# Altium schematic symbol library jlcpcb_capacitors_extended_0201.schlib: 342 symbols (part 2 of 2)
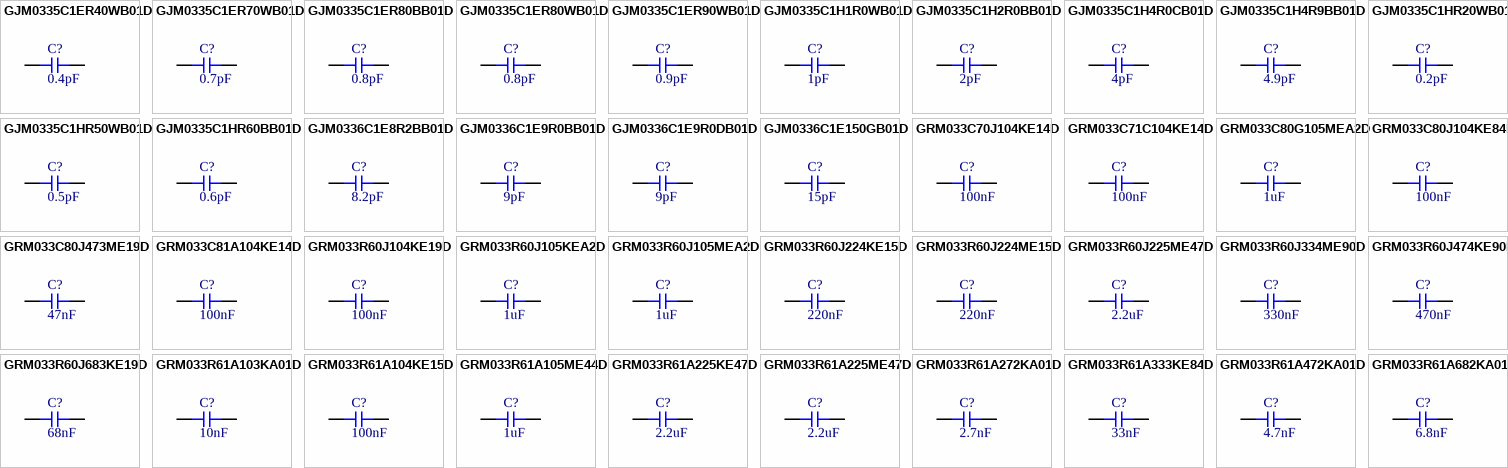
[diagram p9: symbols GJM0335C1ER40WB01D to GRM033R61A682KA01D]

## GRM033C81A104KE14D
designator C?  Capacitance: 100nF  (hidden comment: *)
Capacitor, Ceramic (MLCC), 100nF, ±10%, ±10%, SMD 0201; Manufacturer: Murata Electronics; Manufacturer Part Number: GRM033C81A104KE14D
footprint CAP-0201 (0201 (0603M) Capacitor)
pins: 1, 2

## GRM033R60J104KE19D
designator C?  Capacitance: 100nF  (hidden comment: *)
Capacitor, Ceramic (MLCC), 100nF, ±10%, 6.3V, X5R, ±10%, SMD 0201; Manufacturer: Murata Electronics; Manufacturer Part Number: GRM033R60J104KE19D
footprint CAP-0201 (0201 (0603M) Capacitor)
pins: 1, 2

## GRM033R60J105KEA2D
designator C?  Capacitance: 1uF  (hidden comment: *)
Capacitor, Ceramic (MLCC), 1uF, ±10%, 6.3V, X5R, ±10%, SMD 0201; Manufacturer: Murata Electronics; Manufacturer Part Number: GRM033R60J105KEA2D
footprint CAP-0201 (0201 (0603M) Capacitor)
pins: 1, 2

## GRM033R60J105MEA2D
designator C?  Capacitance: 1uF  (hidden comment: *)
Capacitor, Ceramic (MLCC), 1uF, ±20%, 6.3V, X5R, ±20%, SMD 0201; Manufacturer: Murata Electronics; Manufacturer Part Number: GRM033R60J105MEA2D
footprint CAP-0201 (0201 (0603M) Capacitor)
pins: 1, 2

## GRM033R60J224KE15D
designator C?  Capacitance: 220nF  (hidden comment: *)
Capacitor, Ceramic (MLCC), 220nF, ±10%, 6.3V, X5R, ±10%, SMD 0201; Manufacturer: Murata Electronics; Manufacturer Part Number: GRM033R60J224KE15D
footprint CAP-0201 (0201 (0603M) Capacitor)
pins: 1, 2

## GRM033R60J224ME15D
designator C?  Capacitance: 220nF  (hidden comment: *)
Capacitor, Ceramic (MLCC), 220nF, ±20%, 6.3V, X5R, ±20%, SMD 0201; Manufacturer: Murata Electronics; Manufacturer Part Number: GRM033R60J224ME15D
footprint CAP-0201 (0201 (0603M) Capacitor)
pins: 1, 2

## GRM033R60J225ME47D
designator C?  Capacitance: 2.2uF  (hidden comment: *)
Capacitor, Ceramic (MLCC), 2.2uF, ±20%, 6.3V, X5R, ±20%, SMD 0201; Manufacturer: Murata Electronics; Manufacturer Part Number: GRM033R60J225ME47D
footprint CAP-0201 (0201 (0603M) Capacitor)
pins: 1, 2

## GRM033R60J334ME90D
designator C?  Capacitance: 330nF  (hidden comment: *)
Capacitor, Ceramic (MLCC), 330nF, ±20%, 6.3V, X5R, ±20%, SMD 0201; Manufacturer: Murata Electronics; Manufacturer Part Number: GRM033R60J334ME90D
footprint CAP-0201 (0201 (0603M) Capacitor)
pins: 1, 2

## GRM033R60J474KE90D
designator C?  Capacitance: 470nF  (hidden comment: *)
Capacitor, Ceramic (MLCC), 470nF, ±10%, 6.3V, X5R, ±10%, SMD 0201; Manufacturer: Murata Electronics; Manufacturer Part Number: GRM033R60J474KE90D
footprint CAP-0201 (0201 (0603M) Capacitor)
pins: 1, 2

## GRM033R60J683KE19D
designator C?  Capacitance: 68nF  (hidden comment: *)
Capacitor, Ceramic (MLCC), 68nF, ±10%, 6.3V, X5R, ±10%, SMD 0201; Manufacturer: Murata Electronics; Manufacturer Part Number: GRM033R60J683KE19D
footprint CAP-0201 (0201 (0603M) Capacitor)
pins: 1, 2

## GRM033R61A103KA01D
designator C?  Capacitance: 10nF  (hidden comment: *)
Capacitor, Ceramic (MLCC), 10nF, ±10%, 10V, X5R, ±10%, SMD 0201; Manufacturer: Murata Electronics; Manufacturer Part Number: GRM033R61A103KA01D
footprint CAP-0201 (0201 (0603M) Capacitor)
pins: 1, 2

## GRM033R61A104KE15D
designator C?  Capacitance: 100nF  (hidden comment: *)
Capacitor, Ceramic (MLCC), 100nF, ±10%, 10V, X5R, ±10%, SMD 0201; Manufacturer: Murata Electronics; Manufacturer Part Number: GRM033R61A104KE15D
footprint CAP-0201 (0201 (0603M) Capacitor)
pins: 1, 2

## GRM033R61A105ME44D
designator C?  Capacitance: 1uF  (hidden comment: *)
Capacitor, Ceramic (MLCC), 1uF, ±20%, 10V, X5R, ±20%, SMD 0201; Manufacturer: Murata Electronics; Manufacturer Part Number: GRM033R61A105ME44D
footprint CAP-0201 (0201 (0603M) Capacitor)
pins: 1, 2

## GRM033R61A225KE47D
designator C?  Capacitance: 2.2uF  (hidden comment: *)
Capacitor, Ceramic (MLCC), 2.2uF, ±10%, 10V, X5R, ±10%, SMD 0201; Manufacturer: Murata Electronics; Manufacturer Part Number: GRM033R61A225KE47D
footprint CAP-0201 (0201 (0603M) Capacitor)
pins: 1, 2

## GRM033R61A225ME47D
designator C?  Capacitance: 2.2uF  (hidden comment: *)
Capacitor, Ceramic (MLCC), 2.2uF, ±20%, 10V, X5R, ±20%, SMD 0201; Manufacturer: Murata Electronics; Manufacturer Part Number: GRM033R61A225ME47D
footprint CAP-0201 (0201 (0603M) Capacitor)
pins: 1, 2

## GRM033R61A272KA01D
designator C?  Capacitance: 2.7nF  (hidden comment: *)
Capacitor, Ceramic (MLCC), 2.7nF, ±10%, ±10%, SMD 0201; Manufacturer: Murata Electronics; Manufacturer Part Number: GRM033R61A272KA01D
footprint CAP-0201 (0201 (0603M) Capacitor)
pins: 1, 2

## GRM033R61A333KE84D
designator C?  Capacitance: 33nF  (hidden comment: *)
Capacitor, Ceramic (MLCC), 33nF, ±10%, 10V, X5R, ±10%, SMD 0201; Manufacturer: Murata Electronics; Manufacturer Part Number: GRM033R61A333KE84D
footprint CAP-0201 (0201 (0603M) Capacitor)
pins: 1, 2

## GRM033R61A472KA01D
designator C?  Capacitance: 4.7nF  (hidden comment: *)
Capacitor, Ceramic (MLCC), 4.7nF, ±10%, 10V, X5R, ±10%, SMD 0201; Manufacturer: Murata Electronics; Manufacturer Part Number: GRM033R61A472KA01D
footprint CAP-0201 (0201 (0603M) Capacitor)
pins: 1, 2

## GRM033R61A682KA01D
designator C?  Capacitance: 6.8nF  (hidden comment: *)
Capacitor, Ceramic (MLCC), 6.8nF, ±10%, 10V, X5R, ±10%, SMD 0201; Manufacturer: Murata Electronics; Manufacturer Part Number: GRM033R61A682KA01D
footprint CAP-0201 (0201 (0603M) Capacitor)
pins: 1, 2

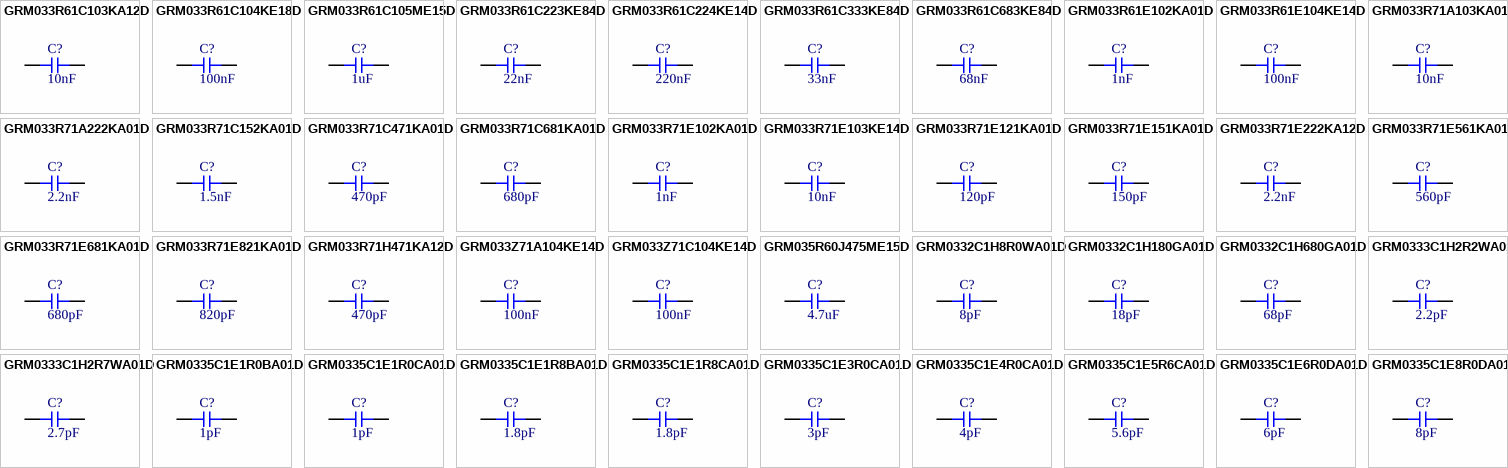
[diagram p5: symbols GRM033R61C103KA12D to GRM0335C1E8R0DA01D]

## GRM033R61C103KA12D
designator C?  Capacitance: 10nF  (hidden comment: *)
Capacitor, Ceramic (MLCC), 10nF, ±10%, 16V, X5R, ±10%, SMD 0201; Manufacturer: Murata Electronics; Manufacturer Part Number: GRM033R61C103KA12D
footprint CAP-0201 (0201 (0603M) Capacitor)
pins: 1, 2

## GRM033R61C104KE18D
designator C?  Capacitance: 100nF  (hidden comment: *)
Capacitor, Ceramic (MLCC), 100nF, ±10%, 16V, X5R, ±10%, SMD 0201; Manufacturer: Murata Electronics; Manufacturer Part Number: GRM033R61C104KE18D
footprint CAP-0201 (0201 (0603M) Capacitor)
pins: 1, 2

## GRM033R61C105ME15D
designator C?  Capacitance: 1uF  (hidden comment: *)
Capacitor, Ceramic (MLCC), 1uF, ±20%, 16V, X5R, ±20%, SMD 0201; Manufacturer: Murata Electronics; Manufacturer Part Number: GRM033R61C105ME15D
footprint CAP-0201 (0201 (0603M) Capacitor)
pins: 1, 2

## GRM033R61C223KE84D
designator C?  Capacitance: 22nF  (hidden comment: *)
Capacitor, Ceramic (MLCC), 22nF, ±10%, 16V, X5R, ±10%, SMD 0201; Manufacturer: Murata Electronics; Manufacturer Part Number: GRM033R61C223KE84D
footprint CAP-0201 (0201 (0603M) Capacitor)
pins: 1, 2

## GRM033R61C224KE14D
designator C?  Capacitance: 220nF  (hidden comment: *)
Capacitor, Ceramic (MLCC), 220nF, ±10%, 16V, X5R, ±10%, SMD 0201; Manufacturer: Murata Electronics; Manufacturer Part Number: GRM033R61C224KE14D
footprint CAP-0201 (0201 (0603M) Capacitor)
pins: 1, 2

## GRM033R61C333KE84D
designator C?  Capacitance: 33nF  (hidden comment: *)
Capacitor, Ceramic (MLCC), 33nF, ±10%, 16V, X5R, ±10%, SMD 0201; Manufacturer: Murata Electronics; Manufacturer Part Number: GRM033R61C333KE84D
footprint CAP-0201 (0201 (0603M) Capacitor)
pins: 1, 2

## GRM033R61C683KE84D
designator C?  Capacitance: 68nF  (hidden comment: *)
Capacitor, Ceramic (MLCC), 68nF, ±10%, 16V, ±10%, SMD 0201; Manufacturer: Murata Electronics; Manufacturer Part Number: GRM033R61C683KE84D
footprint CAP-0201 (0201 (0603M) Capacitor)
pins: 1, 2

## GRM033R61E102KA01D
designator C?  Capacitance: 1nF  (hidden comment: *)
Capacitor, Ceramic (MLCC), 1nF, ±10%, 25V, X5R, ±10%, SMD 0201; Manufacturer: Murata Electronics; Manufacturer Part Number: GRM033R61E102KA01D
footprint CAP-0201 (0201 (0603M) Capacitor)
pins: 1, 2

## GRM033R61E104KE14D
designator C?  Capacitance: 100nF  (hidden comment: *)
Capacitor, Ceramic (MLCC), 100nF, ±10%, 25V, X5R, ±10%, SMD 0201; Manufacturer: Murata Electronics; Manufacturer Part Number: GRM033R61E104KE14D
footprint CAP-0201 (0201 (0603M) Capacitor)
pins: 1, 2

## GRM033R71A103KA01D
designator C?  Capacitance: 10nF  (hidden comment: *)
Capacitor, Ceramic (MLCC), 10nF, ±10%, 10V, X7R, ±10%, SMD 0201; Manufacturer: Murata Electronics; Manufacturer Part Number: GRM033R71A103KA01D
footprint CAP-0201 (0201 (0603M) Capacitor)
pins: 1, 2

## GRM033R71A222KA01D
designator C?  Capacitance: 2.2nF  (hidden comment: *)
Capacitor, Ceramic (MLCC), 2.2nF, ±10%, 10V, X7R, ±10%, SMD 0201; Manufacturer: Murata Electronics; Manufacturer Part Number: GRM033R71A222KA01D
footprint CAP-0201 (0201 (0603M) Capacitor)
pins: 1, 2

## GRM033R71C152KA01D
designator C?  Capacitance: 1.5nF  (hidden comment: *)
Capacitor, Ceramic (MLCC), 1.5nF, ±10%, 16V, X7R, ±10%, SMD 0201; Manufacturer: Murata Electronics; Manufacturer Part Number: GRM033R71C152KA01D
footprint CAP-0201 (0201 (0603M) Capacitor)
pins: 1, 2

## GRM033R71C471KA01D
designator C?  Capacitance: 470pF  (hidden comment: *)
Capacitor, Ceramic (MLCC), 470pF, ±10%, 16V, X7R, ±10%, SMD 0201; Manufacturer: Murata Electronics; Manufacturer Part Number: GRM033R71C471KA01D
footprint CAP-0201 (0201 (0603M) Capacitor)
pins: 1, 2

## GRM033R71C681KA01D
designator C?  Capacitance: 680pF  (hidden comment: *)
Capacitor, Ceramic (MLCC), 680pF, ±10%, 16V, X7R, ±10%, SMD 0201; Manufacturer: Murata Electronics; Manufacturer Part Number: GRM033R71C681KA01D
footprint CAP-0201 (0201 (0603M) Capacitor)
pins: 1, 2

## GRM033R71E102KA01D
designator C?  Capacitance: 1nF  (hidden comment: *)
Capacitor, Ceramic (MLCC), 1nF, ±10%, 25V, X7R, ±10%, SMD 0201; Manufacturer: Murata Electronics; Manufacturer Part Number: GRM033R71E102KA01D
footprint CAP-0201 (0201 (0603M) Capacitor)
pins: 1, 2

## GRM033R71E103KE14D
designator C?  Capacitance: 10nF  (hidden comment: *)
Capacitor, Ceramic (MLCC), 10nF, ±10%, 25V, X7R, ±10%, SMD 0201; Manufacturer: Murata Electronics; Manufacturer Part Number: GRM033R71E103KE14D
footprint CAP-0201 (0201 (0603M) Capacitor)
pins: 1, 2

## GRM033R71E121KA01D
designator C?  Capacitance: 120pF  (hidden comment: *)
Capacitor, Ceramic (MLCC), 120pF, ±10%, 25V, ±10%, SMD 0201; Manufacturer: Murata Electronics; Manufacturer Part Number: GRM033R71E121KA01D
footprint CAP-0201 (0201 (0603M) Capacitor)
pins: 1, 2

## GRM033R71E151KA01D
designator C?  Capacitance: 150pF  (hidden comment: *)
Capacitor, Ceramic (MLCC), 150pF, ±10%, 25V, X7R, ±10%, SMD 0201; Manufacturer: Murata Electronics; Manufacturer Part Number: GRM033R71E151KA01D
footprint CAP-0201 (0201 (0603M) Capacitor)
pins: 1, 2

## GRM033R71E222KA12D
designator C?  Capacitance: 2.2nF  (hidden comment: *)
Capacitor, Ceramic (MLCC), 2.2nF, ±10%, 25V, X7R, ±10%, SMD 0201; Manufacturer: Murata Electronics; Manufacturer Part Number: GRM033R71E222KA12D
footprint CAP-0201 (0201 (0603M) Capacitor)
pins: 1, 2

## GRM033R71E561KA01D
designator C?  Capacitance: 560pF  (hidden comment: *)
Capacitor, Ceramic (MLCC), 560pF, ±10%, 25V, X7R, ±10%, SMD 0201; Manufacturer: Murata Electronics; Manufacturer Part Number: GRM033R71E561KA01D
footprint CAP-0201 (0201 (0603M) Capacitor)
pins: 1, 2

## GRM033R71E681KA01D
designator C?  Capacitance: 680pF  (hidden comment: *)
Capacitor, Ceramic (MLCC), 680pF, ±10%, 25V, X7R, ±10%, SMD 0201; Manufacturer: Murata Electronics; Manufacturer Part Number: GRM033R71E681KA01D
footprint CAP-0201 (0201 (0603M) Capacitor)
pins: 1, 2

## GRM033R71E821KA01D
designator C?  Capacitance: 820pF  (hidden comment: *)
Capacitor, Ceramic (MLCC), 820pF, ±10%, 25V, X7R, ±10%, SMD 0201; Manufacturer: Murata Electronics; Manufacturer Part Number: GRM033R71E821KA01D
footprint CAP-0201 (0201 (0603M) Capacitor)
pins: 1, 2

## GRM033R71H471KA12D
designator C?  Capacitance: 470pF  (hidden comment: *)
Capacitor, Ceramic (MLCC), 470pF, ±10%, 50V, X7R, ±10%, SMD 0201; Manufacturer: Murata Electronics; Manufacturer Part Number: GRM033R71H471KA12D
footprint CAP-0201 (0201 (0603M) Capacitor)
pins: 1, 2

## GRM033Z71A104KE14D
designator C?  Capacitance: 100nF  (hidden comment: *)
Capacitor, Ceramic (MLCC), 100nF, ±10%, 10V, X7R, ±10%, SMD 0201; Manufacturer: Murata Electronics; Manufacturer Part Number: GRM033Z71A104KE14D
footprint CAP-0201 (0201 (0603M) Capacitor)
pins: 1, 2

## GRM033Z71C104KE14D
designator C?  Capacitance: 100nF  (hidden comment: *)
Capacitor, Ceramic (MLCC), 100nF, ±10%, ±10%, SMD 0201; Manufacturer: Murata Electronics; Manufacturer Part Number: GRM033Z71C104KE14D
footprint CAP-0201 (0201 (0603M) Capacitor)
pins: 1, 2

## GRM035R60J475ME15D
designator C?  Capacitance: 4.7uF  (hidden comment: *)
Capacitor, Ceramic (MLCC), 4.7uF, ±20%, 6.3V, X5R, ±20%, SMD 0201; Manufacturer: Murata Electronics; Manufacturer Part Number: GRM035R60J475ME15D
footprint CAP-0201 (0201 (0603M) Capacitor)
pins: 1, 2

## GRM0332C1H8R0WA01D
designator C?  Capacitance: 8pF  (hidden comment: *)
Capacitor, Ceramic (MLCC), 8pF, ±0.05pF, 50V, CH, ±0.05pF, SMD 0201; Manufacturer: Murata Electronics; Manufacturer Part Number: GRM0332C1H8R0WA01D
footprint CAP-0201 (0201 (0603M) Capacitor)
pins: 1, 2

## GRM0332C1H180GA01D
designator C?  Capacitance: 18pF  (hidden comment: *)
Capacitor, Ceramic (MLCC), 18pF, ±2%, 50V, CH, ±2%, SMD 0201; Manufacturer: Murata Electronics; Manufacturer Part Number: GRM0332C1H180GA01D
footprint CAP-0201 (0201 (0603M) Capacitor)
pins: 1, 2

## GRM0332C1H680GA01D
designator C?  Capacitance: 68pF  (hidden comment: *)
Capacitor, Ceramic (MLCC), 68pF, ±2%, 50V, CH, ±2%, SMD 0201; Manufacturer: Murata Electronics; Manufacturer Part Number: GRM0332C1H680GA01D
footprint CAP-0201 (0201 (0603M) Capacitor)
pins: 1, 2

## GRM0333C1H2R2WA01D
designator C?  Capacitance: 2.2pF  (hidden comment: *)
Capacitor, Ceramic (MLCC), 2.2pF, ±0.05pF, 50V, CJ, ±0.05pF, SMD 0201; Manufacturer: Murata Electronics; Manufacturer Part Number: GRM0333C1H2R2WA01D
footprint CAP-0201 (0201 (0603M) Capacitor)
pins: 1, 2

## GRM0333C1H2R7WA01D
designator C?  Capacitance: 2.7pF  (hidden comment: *)
Capacitor, Ceramic (MLCC), 2.7pF, ±0.05pF, 50V, CJ, ±0.05pF, SMD 0201; Manufacturer: Murata Electronics; Manufacturer Part Number: GRM0333C1H2R7WA01D
footprint CAP-0201 (0201 (0603M) Capacitor)
pins: 1, 2

## GRM0335C1E1R0BA01D
designator C?  Capacitance: 1pF  (hidden comment: *)
Capacitor, Ceramic (MLCC), 1pF, ±0.1pF, 25V, C0G, ±0.1pF, SMD 0201; Manufacturer: Murata Electronics; Manufacturer Part Number: GRM0335C1E1R0BA01D
footprint CAP-0201 (0201 (0603M) Capacitor)
pins: 1, 2

## GRM0335C1E1R0CA01D
designator C?  Capacitance: 1pF  (hidden comment: *)
Capacitor, Ceramic (MLCC), 1pF, ±0.25pF, 25V, C0G, ±0.25pF, SMD 0201; Manufacturer: Murata Electronics; Manufacturer Part Number: GRM0335C1E1R0CA01D
footprint CAP-0201 (0201 (0603M) Capacitor)
pins: 1, 2

## GRM0335C1E1R8BA01D
designator C?  Capacitance: 1.8pF  (hidden comment: *)
Capacitor, Ceramic (MLCC), 1.8pF, ±0.1pF, 25V, C0G, ±0.1pF, SMD 0201; Manufacturer: Murata Electronics; Manufacturer Part Number: GRM0335C1E1R8BA01D
footprint CAP-0201 (0201 (0603M) Capacitor)
pins: 1, 2

## GRM0335C1E1R8CA01D
designator C?  Capacitance: 1.8pF  (hidden comment: *)
Capacitor, Ceramic (MLCC), 1.8pF, ±0.25pF, 25V, C0G, ±0.25pF, SMD 0201; Manufacturer: Murata Electronics; Manufacturer Part Number: GRM0335C1E1R8CA01D
footprint CAP-0201 (0201 (0603M) Capacitor)
pins: 1, 2

## GRM0335C1E3R0CA01D
designator C?  Capacitance: 3pF  (hidden comment: *)
Capacitor, Ceramic (MLCC), 3pF, ±0.25pF, 25V, C0G, ±0.25pF, SMD 0201; Manufacturer: Murata Electronics; Manufacturer Part Number: GRM0335C1E3R0CA01D
footprint CAP-0201 (0201 (0603M) Capacitor)
pins: 1, 2

## GRM0335C1E4R0CA01D
designator C?  Capacitance: 4pF  (hidden comment: *)
Capacitor, Ceramic (MLCC), 4pF, ±0.25pF, 25V, C0G, ±0.25pF, SMD 0201; Manufacturer: Murata Electronics; Manufacturer Part Number: GRM0335C1E4R0CA01D
footprint CAP-0201 (0201 (0603M) Capacitor)
pins: 1, 2

## GRM0335C1E5R6CA01D
designator C?  Capacitance: 5.6pF  (hidden comment: *)
Capacitor, Ceramic (MLCC), 5.6pF, ±0.25pF, 25V, C0G, ±0.25pF, SMD 0201; Manufacturer: Murata Electronics; Manufacturer Part Number: GRM0335C1E5R6CA01D
footprint CAP-0201 (0201 (0603M) Capacitor)
pins: 1, 2

## GRM0335C1E6R0DA01D
designator C?  Capacitance: 6pF  (hidden comment: *)
Capacitor, Ceramic (MLCC), 6pF, ±0.5pF, 25V, C0G, ±0.5pF, SMD 0201; Manufacturer: Murata Electronics; Manufacturer Part Number: GRM0335C1E6R0DA01D
footprint CAP-0201 (0201 (0603M) Capacitor)
pins: 1, 2

## GRM0335C1E8R0DA01D
designator C?  Capacitance: 8pF  (hidden comment: *)
Capacitor, Ceramic (MLCC), 8pF, ±0.5pF, 25V, C0G, ±0.5pF, SMD 0201; Manufacturer: Murata Electronics; Manufacturer Part Number: GRM0335C1E8R0DA01D
footprint CAP-0201 (0201 (0603M) Capacitor)
pins: 1, 2

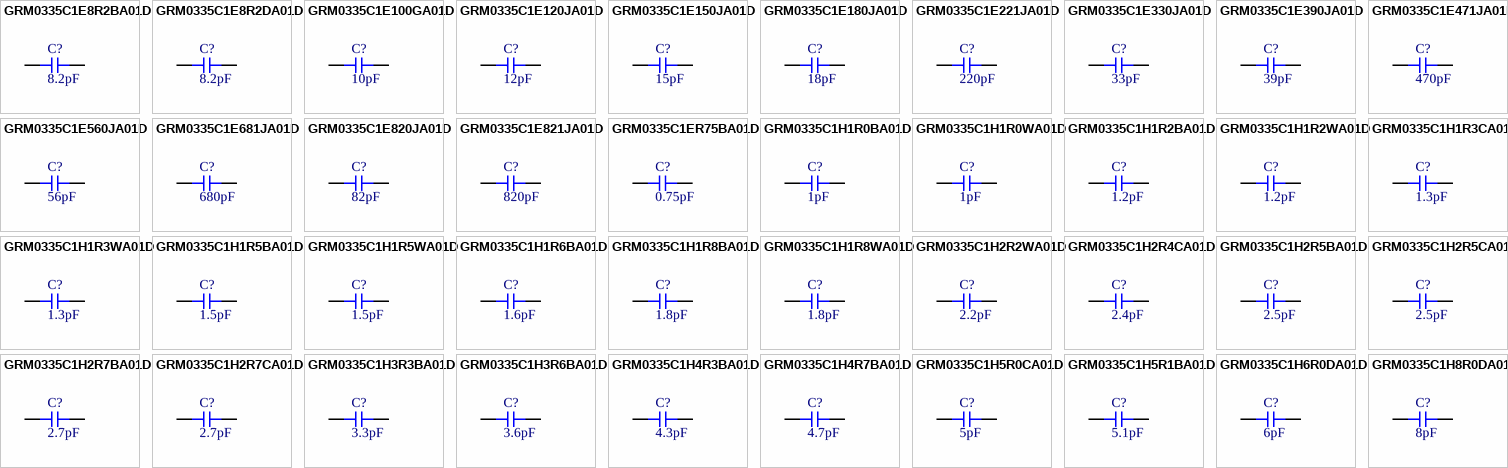
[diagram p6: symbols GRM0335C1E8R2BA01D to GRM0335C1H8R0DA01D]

## GRM0335C1E8R2BA01D
designator C?  Capacitance: 8.2pF  (hidden comment: *)
Capacitor, Ceramic (MLCC), 8.2pF, ±0.1pF, 25V, C0G, ±0.1pF, SMD 0201; Manufacturer: Murata Electronics; Manufacturer Part Number: GRM0335C1E8R2BA01D
footprint CAP-0201 (0201 (0603M) Capacitor)
pins: 1, 2

## GRM0335C1E8R2DA01D
designator C?  Capacitance: 8.2pF  (hidden comment: *)
Capacitor, Ceramic (MLCC), 8.2pF, ±0.5pF, 25V, C0G, ±0.5pF, SMD 0201; Manufacturer: Murata Electronics; Manufacturer Part Number: GRM0335C1E8R2DA01D
footprint CAP-0201 (0201 (0603M) Capacitor)
pins: 1, 2

## GRM0335C1E100GA01D
designator C?  Capacitance: 10pF  (hidden comment: *)
Capacitor, Ceramic (MLCC), 10pF, ±2%, 25V, C0G, ±2%, SMD 0201; Manufacturer: Murata Electronics; Manufacturer Part Number: GRM0335C1E100GA01D
footprint CAP-0201 (0201 (0603M) Capacitor)
pins: 1, 2

## GRM0335C1E120JA01D
designator C?  Capacitance: 12pF  (hidden comment: *)
Capacitor, Ceramic (MLCC), 12pF, ±5%, 25V, C0G, ±5%, SMD 0201; Manufacturer: Murata Electronics; Manufacturer Part Number: GRM0335C1E120JA01D
footprint CAP-0201 (0201 (0603M) Capacitor)
pins: 1, 2

## GRM0335C1E150JA01D
designator C?  Capacitance: 15pF  (hidden comment: *)
Capacitor, Ceramic (MLCC), 15pF, ±5%, 25V, C0G, ±5%, SMD 0201; Manufacturer: Murata Electronics; Manufacturer Part Number: GRM0335C1E150JA01D
footprint CAP-0201 (0201 (0603M) Capacitor)
pins: 1, 2

## GRM0335C1E180JA01D
designator C?  Capacitance: 18pF  (hidden comment: *)
Capacitor, Ceramic (MLCC), 18pF, ±5%, 25V, C0G, ±5%, SMD 0201; Manufacturer: Murata Electronics; Manufacturer Part Number: GRM0335C1E180JA01D
footprint CAP-0201 (0201 (0603M) Capacitor)
pins: 1, 2

## GRM0335C1E221JA01D
designator C?  Capacitance: 220pF  (hidden comment: *)
Capacitor, Ceramic (MLCC), 220pF, ±5%, 25V, C0G, ±5%, SMD 0201; Manufacturer: Murata Electronics; Manufacturer Part Number: GRM0335C1E221JA01D
footprint CAP-0201 (0201 (0603M) Capacitor)
pins: 1, 2

## GRM0335C1E330JA01D
designator C?  Capacitance: 33pF  (hidden comment: *)
Capacitor, Ceramic (MLCC), 33pF, ±5%, 25V, C0G, ±5%, SMD 0201; Manufacturer: Murata Electronics; Manufacturer Part Number: GRM0335C1E330JA01D
footprint CAP-0201 (0201 (0603M) Capacitor)
pins: 1, 2

## GRM0335C1E390JA01D
designator C?  Capacitance: 39pF  (hidden comment: *)
Capacitor, Ceramic (MLCC), 39pF, ±5%, 25V, C0G, ±5%, SMD 0201; Manufacturer: Murata Electronics; Manufacturer Part Number: GRM0335C1E390JA01D
footprint CAP-0201 (0201 (0603M) Capacitor)
pins: 1, 2

## GRM0335C1E471JA01D
designator C?  Capacitance: 470pF  (hidden comment: *)
Capacitor, Ceramic (MLCC), 470pF, ±5%, 25V, C0G, ±5%, SMD 0201; Manufacturer: Murata Electronics; Manufacturer Part Number: GRM0335C1E471JA01D
footprint CAP-0201 (0201 (0603M) Capacitor)
pins: 1, 2

## GRM0335C1E560JA01D
designator C?  Capacitance: 56pF  (hidden comment: *)
Capacitor, Ceramic (MLCC), 56pF, ±5%, 25V, C0G, ±5%, SMD 0201; Manufacturer: Murata Electronics; Manufacturer Part Number: GRM0335C1E560JA01D
footprint CAP-0201 (0201 (0603M) Capacitor)
pins: 1, 2

## GRM0335C1E681JA01D
designator C?  Capacitance: 680pF  (hidden comment: *)
Capacitor, Ceramic (MLCC), 680pF, ±5%, 25V, C0G, ±5%, SMD 0201; Manufacturer: Murata Electronics; Manufacturer Part Number: GRM0335C1E681JA01D
footprint CAP-0201 (0201 (0603M) Capacitor)
pins: 1, 2

## GRM0335C1E820JA01D
designator C?  Capacitance: 82pF  (hidden comment: *)
Capacitor, Ceramic (MLCC), 82pF, ±5%, 25V, C0G, ±5%, SMD 0201; Manufacturer: Murata Electronics; Manufacturer Part Number: GRM0335C1E820JA01D
footprint CAP-0201 (0201 (0603M) Capacitor)
pins: 1, 2

## GRM0335C1E821JA01D
designator C?  Capacitance: 820pF  (hidden comment: *)
Capacitor, Ceramic (MLCC), 820pF, ±5%, 25V, C0G, ±5%, SMD 0201; Manufacturer: Murata Electronics; Manufacturer Part Number: GRM0335C1E821JA01D
footprint CAP-0201 (0201 (0603M) Capacitor)
pins: 1, 2

## GRM0335C1ER75BA01D
designator C?  Capacitance: 0.75pF  (hidden comment: *)
Capacitor, Ceramic (MLCC), 0.75pF, ±0.1pF, 25V, C0G, ±0.1pF, SMD 0201; Manufacturer: Murata Electronics; Manufacturer Part Number: GRM0335C1ER75BA01D
footprint CAP-0201 (0201 (0603M) Capacitor)
pins: 1, 2

## GRM0335C1H1R0BA01D
designator C?  Capacitance: 1pF  (hidden comment: *)
Capacitor, Ceramic (MLCC), 1pF, ±0.1pF, 50V, C0G, ±0.1pF, SMD 0201; Manufacturer: Murata Electronics; Manufacturer Part Number: GRM0335C1H1R0BA01D
footprint CAP-0201 (0201 (0603M) Capacitor)
pins: 1, 2

## GRM0335C1H1R0WA01D
designator C?  Capacitance: 1pF  (hidden comment: *)
Capacitor, Ceramic (MLCC), 1pF, ±0.05pF, 50V, C0G, ±0.05pF, SMD 0201; Manufacturer: Murata Electronics; Manufacturer Part Number: GRM0335C1H1R0WA01D
footprint CAP-0201 (0201 (0603M) Capacitor)
pins: 1, 2

## GRM0335C1H1R2BA01D
designator C?  Capacitance: 1.2pF  (hidden comment: *)
Capacitor, Ceramic (MLCC), 1.2pF, ±0.1pF, 50V, C0G, ±0.1pF, SMD 0201; Manufacturer: Murata Electronics; Manufacturer Part Number: GRM0335C1H1R2BA01D
footprint CAP-0201 (0201 (0603M) Capacitor)
pins: 1, 2

## GRM0335C1H1R2WA01D
designator C?  Capacitance: 1.2pF  (hidden comment: *)
Capacitor, Ceramic (MLCC), 1.2pF, ±0.05pF, 50V, C0G, ±0.05pF, SMD 0201; Manufacturer: Murata Electronics; Manufacturer Part Number: GRM0335C1H1R2WA01D
footprint CAP-0201 (0201 (0603M) Capacitor)
pins: 1, 2

## GRM0335C1H1R3CA01D
designator C?  Capacitance: 1.3pF  (hidden comment: *)
Capacitor, Ceramic (MLCC), 1.3pF, ±0.25pF, 50V, C0G, ±0.25pF, SMD 0201; Manufacturer: Murata Electronics; Manufacturer Part Number: GRM0335C1H1R3CA01D
footprint CAP-0201 (0201 (0603M) Capacitor)
pins: 1, 2

## GRM0335C1H1R3WA01D
designator C?  Capacitance: 1.3pF  (hidden comment: *)
Capacitor, Ceramic (MLCC), 1.3pF, ±0.05pF, 50V, C0G, ±0.05pF, SMD 0201; Manufacturer: Murata Electronics; Manufacturer Part Number: GRM0335C1H1R3WA01D
footprint CAP-0201 (0201 (0603M) Capacitor)
pins: 1, 2

## GRM0335C1H1R5BA01D
designator C?  Capacitance: 1.5pF  (hidden comment: *)
Capacitor, Ceramic (MLCC), 1.5pF, ±0.1pF, 50V, C0G, ±0.1pF, SMD 0201; Manufacturer: Murata Electronics; Manufacturer Part Number: GRM0335C1H1R5BA01D
footprint CAP-0201 (0201 (0603M) Capacitor)
pins: 1, 2

## GRM0335C1H1R5WA01D
designator C?  Capacitance: 1.5pF  (hidden comment: *)
Capacitor, Ceramic (MLCC), 1.5pF, ±0.05pF, 50V, C0G, ±0.05pF, SMD 0201; Manufacturer: Murata Electronics; Manufacturer Part Number: GRM0335C1H1R5WA01D
footprint CAP-0201 (0201 (0603M) Capacitor)
pins: 1, 2

## GRM0335C1H1R6BA01D
designator C?  Capacitance: 1.6pF  (hidden comment: *)
Capacitor, Ceramic (MLCC), 1.6pF, ±0.1pF, 50V, C0G, ±0.1pF, SMD 0201; Manufacturer: Murata Electronics; Manufacturer Part Number: GRM0335C1H1R6BA01D
footprint CAP-0201 (0201 (0603M) Capacitor)
pins: 1, 2

## GRM0335C1H1R8BA01D
designator C?  Capacitance: 1.8pF  (hidden comment: *)
Capacitor, Ceramic (MLCC), 1.8pF, ±0.1pF, 50V, C0G, ±0.1pF, SMD 0201; Manufacturer: Murata Electronics; Manufacturer Part Number: GRM0335C1H1R8BA01D
footprint CAP-0201 (0201 (0603M) Capacitor)
pins: 1, 2

## GRM0335C1H1R8WA01D
designator C?  Capacitance: 1.8pF  (hidden comment: *)
Capacitor, Ceramic (MLCC), 1.8pF, ±0.05pF, 50V, C0G, ±0.05pF, SMD 0201; Manufacturer: Murata Electronics; Manufacturer Part Number: GRM0335C1H1R8WA01D
footprint CAP-0201 (0201 (0603M) Capacitor)
pins: 1, 2

## GRM0335C1H2R2WA01D
designator C?  Capacitance: 2.2pF  (hidden comment: *)
Capacitor, Ceramic (MLCC), 2.2pF, ±0.05pF, 50V, C0G, ±0.05pF, SMD 0201; Manufacturer: Murata Electronics; Manufacturer Part Number: GRM0335C1H2R2WA01D
footprint CAP-0201 (0201 (0603M) Capacitor)
pins: 1, 2

## GRM0335C1H2R4CA01D
designator C?  Capacitance: 2.4pF  (hidden comment: *)
Capacitor, Ceramic (MLCC), 2.4pF, ±0.25pF, 50V, C0G, ±0.25pF, SMD 0201; Manufacturer: Murata Electronics; Manufacturer Part Number: GRM0335C1H2R4CA01D
footprint CAP-0201 (0201 (0603M) Capacitor)
pins: 1, 2

## GRM0335C1H2R5BA01D
designator C?  Capacitance: 2.5pF  (hidden comment: *)
Capacitor, Ceramic (MLCC), 2.5pF, ±0.1pF, 50V, C0G, ±0.1pF, SMD 0201; Manufacturer: Murata Electronics; Manufacturer Part Number: GRM0335C1H2R5BA01D
footprint CAP-0201 (0201 (0603M) Capacitor)
pins: 1, 2

## GRM0335C1H2R5CA01D
designator C?  Capacitance: 2.5pF  (hidden comment: *)
Capacitor, Ceramic (MLCC), 2.5pF, ±0.25pF, 50V, C0G, ±0.25pF, SMD 0201; Manufacturer: Murata Electronics; Manufacturer Part Number: GRM0335C1H2R5CA01D
footprint CAP-0201 (0201 (0603M) Capacitor)
pins: 1, 2

## GRM0335C1H2R7BA01D
designator C?  Capacitance: 2.7pF  (hidden comment: *)
Capacitor, Ceramic (MLCC), 2.7pF, ±0.1pF, 50V, C0G, ±0.1pF, SMD 0201; Manufacturer: Murata Electronics; Manufacturer Part Number: GRM0335C1H2R7BA01D
footprint CAP-0201 (0201 (0603M) Capacitor)
pins: 1, 2

## GRM0335C1H2R7CA01D
designator C?  Capacitance: 2.7pF  (hidden comment: *)
Capacitor, Ceramic (MLCC), 2.7pF, ±0.25pF, 50V, C0G, ±0.25pF, SMD 0201; Manufacturer: Murata Electronics; Manufacturer Part Number: GRM0335C1H2R7CA01D
footprint CAP-0201 (0201 (0603M) Capacitor)
pins: 1, 2

## GRM0335C1H3R3BA01D
designator C?  Capacitance: 3.3pF  (hidden comment: *)
Capacitor, Ceramic (MLCC), 3.3pF, ±0.1pF, 50V, C0G, ±0.1pF, SMD 0201; Manufacturer: Murata Electronics; Manufacturer Part Number: GRM0335C1H3R3BA01D
footprint CAP-0201 (0201 (0603M) Capacitor)
pins: 1, 2

## GRM0335C1H3R6BA01D
designator C?  Capacitance: 3.6pF  (hidden comment: *)
Capacitor, Ceramic (MLCC), 3.6pF, ±0.1pF, 50V, C0G, ±0.1pF, SMD 0201; Manufacturer: Murata Electronics; Manufacturer Part Number: GRM0335C1H3R6BA01D
footprint CAP-0201 (0201 (0603M) Capacitor)
pins: 1, 2

## GRM0335C1H4R3BA01D
designator C?  Capacitance: 4.3pF  (hidden comment: *)
Capacitor, Ceramic (MLCC), 4.3pF, ±0.1pF, 50V, C0G, ±0.1pF, SMD 0201; Manufacturer: Murata Electronics; Manufacturer Part Number: GRM0335C1H4R3BA01D
footprint CAP-0201 (0201 (0603M) Capacitor)
pins: 1, 2

## GRM0335C1H4R7BA01D
designator C?  Capacitance: 4.7pF  (hidden comment: *)
Capacitor, Ceramic (MLCC), 4.7pF, ±0.1pF, 50V, C0G, ±0.1pF, SMD 0201; Manufacturer: Murata Electronics; Manufacturer Part Number: GRM0335C1H4R7BA01D
footprint CAP-0201 (0201 (0603M) Capacitor)
pins: 1, 2

## GRM0335C1H5R0CA01D
designator C?  Capacitance: 5pF  (hidden comment: *)
Capacitor, Ceramic (MLCC), 5pF, ±0.25pF, 50V, C0G, ±0.25pF, SMD 0201; Manufacturer: Murata Electronics; Manufacturer Part Number: GRM0335C1H5R0CA01D
footprint CAP-0201 (0201 (0603M) Capacitor)
pins: 1, 2

## GRM0335C1H5R1BA01D
designator C?  Capacitance: 5.1pF  (hidden comment: *)
Capacitor, Ceramic (MLCC), 5.1pF, ±0.1pF, 50V, C0G, ±0.1pF, SMD 0201; Manufacturer: Murata Electronics; Manufacturer Part Number: GRM0335C1H5R1BA01D
footprint CAP-0201 (0201 (0603M) Capacitor)
pins: 1, 2

## GRM0335C1H6R0DA01D
designator C?  Capacitance: 6pF  (hidden comment: *)
Capacitor, Ceramic (MLCC), 6pF, ±0.5pF, 50V, C0G, ±0.5pF, SMD 0201; Manufacturer: Murata Electronics; Manufacturer Part Number: GRM0335C1H6R0DA01D
footprint CAP-0201 (0201 (0603M) Capacitor)
pins: 1, 2

## GRM0335C1H8R0DA01D
designator C?  Capacitance: 8pF  (hidden comment: *)
Capacitor, Ceramic (MLCC), 8pF, ±0.5pF, 50V, C0G, ±0.5pF, SMD 0201; Manufacturer: Murata Electronics; Manufacturer Part Number: GRM0335C1H8R0DA01D
footprint CAP-0201 (0201 (0603M) Capacitor)
pins: 1, 2

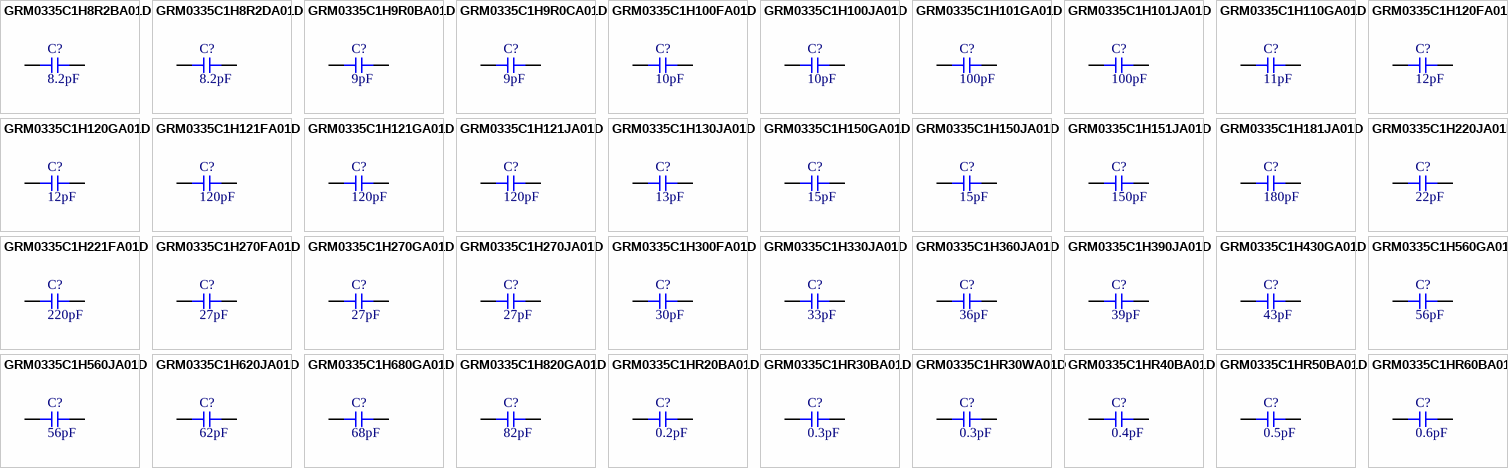
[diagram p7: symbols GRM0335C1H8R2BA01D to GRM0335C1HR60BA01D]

## GRM0335C1H8R2BA01D
designator C?  Capacitance: 8.2pF  (hidden comment: *)
Capacitor, Ceramic (MLCC), 8.2pF, ±0.1pF, 50V, C0G, ±0.1pF, SMD 0201; Manufacturer: Murata Electronics; Manufacturer Part Number: GRM0335C1H8R2BA01D
footprint CAP-0201 (0201 (0603M) Capacitor)
pins: 1, 2

## GRM0335C1H8R2DA01D
designator C?  Capacitance: 8.2pF  (hidden comment: *)
Capacitor, Ceramic (MLCC), 8.2pF, ±0.5pF, 50V, C0G, ±0.5pF, SMD 0201; Manufacturer: Murata Electronics; Manufacturer Part Number: GRM0335C1H8R2DA01D
footprint CAP-0201 (0201 (0603M) Capacitor)
pins: 1, 2

## GRM0335C1H9R0BA01D
designator C?  Capacitance: 9pF  (hidden comment: *)
Capacitor, Ceramic (MLCC), 9pF, ±0.1pF, 50V, C0G, ±0.1pF, SMD 0201; Manufacturer: Murata Electronics; Manufacturer Part Number: GRM0335C1H9R0BA01D
footprint CAP-0201 (0201 (0603M) Capacitor)
pins: 1, 2

## GRM0335C1H9R0CA01D
designator C?  Capacitance: 9pF  (hidden comment: *)
Capacitor, Ceramic (MLCC), 9pF, ±0.25pF, 50V, C0G, ±0.25pF, SMD 0201; Manufacturer: Murata Electronics; Manufacturer Part Number: GRM0335C1H9R0CA01D
footprint CAP-0201 (0201 (0603M) Capacitor)
pins: 1, 2

## GRM0335C1H100FA01D
designator C?  Capacitance: 10pF  (hidden comment: *)
Capacitor, Ceramic (MLCC), 10pF, ±1%, 50V, C0G, ±1%, SMD 0201; Manufacturer: Murata Electronics; Manufacturer Part Number: GRM0335C1H100FA01D
footprint CAP-0201 (0201 (0603M) Capacitor)
pins: 1, 2

## GRM0335C1H100JA01D
designator C?  Capacitance: 10pF  (hidden comment: *)
Capacitor, Ceramic (MLCC), 10pF, ±5%, 50V, C0G, ±5%, SMD 0201; Manufacturer: Murata Electronics; Manufacturer Part Number: GRM0335C1H100JA01D
footprint CAP-0201 (0201 (0603M) Capacitor)
pins: 1, 2

## GRM0335C1H101GA01D
designator C?  Capacitance: 100pF  (hidden comment: *)
Capacitor, Ceramic (MLCC), 100pF, ±2%, 50V, C0G, ±2%, SMD 0201; Manufacturer: Murata Electronics; Manufacturer Part Number: GRM0335C1H101GA01D
footprint CAP-0201 (0201 (0603M) Capacitor)
pins: 1, 2

## GRM0335C1H101JA01D
designator C?  Capacitance: 100pF  (hidden comment: *)
Capacitor, Ceramic (MLCC), 100pF, ±5%, 50V, C0G, ±5%, SMD 0201; Manufacturer: Murata Electronics; Manufacturer Part Number: GRM0335C1H101JA01D
footprint CAP-0201 (0201 (0603M) Capacitor)
pins: 1, 2

## GRM0335C1H110GA01D
designator C?  Capacitance: 11pF  (hidden comment: *)
Capacitor, Ceramic (MLCC), 11pF, ±2%, 50V, C0G, ±2%, SMD 0201; Manufacturer: Murata Electronics; Manufacturer Part Number: GRM0335C1H110GA01D
footprint CAP-0201 (0201 (0603M) Capacitor)
pins: 1, 2

## GRM0335C1H120FA01D
designator C?  Capacitance: 12pF  (hidden comment: *)
Capacitor, Ceramic (MLCC), 12pF, ±1%, 50V, C0G, ±1%, SMD 0201; Manufacturer: Murata Electronics; Manufacturer Part Number: GRM0335C1H120FA01D
footprint CAP-0201 (0201 (0603M) Capacitor)
pins: 1, 2

## GRM0335C1H120GA01D
designator C?  Capacitance: 12pF  (hidden comment: *)
Capacitor, Ceramic (MLCC), 12pF, ±2%, 50V, C0G, ±2%, SMD 0201; Manufacturer: Murata Electronics; Manufacturer Part Number: GRM0335C1H120GA01D
footprint CAP-0201 (0201 (0603M) Capacitor)
pins: 1, 2

## GRM0335C1H121FA01D
designator C?  Capacitance: 120pF  (hidden comment: *)
Capacitor, Ceramic (MLCC), 120pF, ±1%, 50V, ±1%, SMD 0201; Manufacturer: Murata Electronics; Manufacturer Part Number: GRM0335C1H121FA01D
footprint CAP-0201 (0201 (0603M) Capacitor)
pins: 1, 2

## GRM0335C1H121GA01D
designator C?  Capacitance: 120pF  (hidden comment: *)
Capacitor, Ceramic (MLCC), 120pF, ±2%, 50V, C0G, ±2%, SMD 0201; Manufacturer: Murata Electronics; Manufacturer Part Number: GRM0335C1H121GA01D
footprint CAP-0201 (0201 (0603M) Capacitor)
pins: 1, 2

## GRM0335C1H121JA01D
designator C?  Capacitance: 120pF  (hidden comment: *)
Capacitor, Ceramic (MLCC), 120pF, ±5%, 50V, C0G, ±5%, SMD 0201; Manufacturer: Murata Electronics; Manufacturer Part Number: GRM0335C1H121JA01D
footprint CAP-0201 (0201 (0603M) Capacitor)
pins: 1, 2

## GRM0335C1H130JA01D
designator C?  Capacitance: 13pF  (hidden comment: *)
Capacitor, Ceramic (MLCC), 13pF, ±5%, 50V, C0G, ±5%, SMD 0201; Manufacturer: Murata Electronics; Manufacturer Part Number: GRM0335C1H130JA01D
footprint CAP-0201 (0201 (0603M) Capacitor)
pins: 1, 2

## GRM0335C1H150GA01D
designator C?  Capacitance: 15pF  (hidden comment: *)
Capacitor, Ceramic (MLCC), 15pF, ±2%, 50V, C0G, ±2%, SMD 0201; Manufacturer: Murata Electronics; Manufacturer Part Number: GRM0335C1H150GA01D
footprint CAP-0201 (0201 (0603M) Capacitor)
pins: 1, 2

## GRM0335C1H150JA01D
designator C?  Capacitance: 15pF  (hidden comment: *)
Capacitor, Ceramic (MLCC), 15pF, ±5%, 50V, C0G, ±5%, SMD 0201; Manufacturer: Murata Electronics; Manufacturer Part Number: GRM0335C1H150JA01D
footprint CAP-0201 (0201 (0603M) Capacitor)
pins: 1, 2

## GRM0335C1H151JA01D
designator C?  Capacitance: 150pF  (hidden comment: *)
Capacitor, Ceramic (MLCC), 150pF, ±5%, 50V, C0G, ±5%, SMD 0201; Manufacturer: Murata Electronics; Manufacturer Part Number: GRM0335C1H151JA01D
footprint CAP-0201 (0201 (0603M) Capacitor)
pins: 1, 2

## GRM0335C1H181JA01D
designator C?  Capacitance: 180pF  (hidden comment: *)
Capacitor, Ceramic (MLCC), 180pF, ±5%, 50V, C0G, ±5%, SMD 0201; Manufacturer: Murata Electronics; Manufacturer Part Number: GRM0335C1H181JA01D
footprint CAP-0201 (0201 (0603M) Capacitor)
pins: 1, 2

## GRM0335C1H220JA01D
designator C?  Capacitance: 22pF  (hidden comment: *)
Capacitor, Ceramic (MLCC), 22pF, ±5%, 50V, C0G, ±5%, SMD 0201; Manufacturer: Murata Electronics; Manufacturer Part Number: GRM0335C1H220JA01D
footprint CAP-0201 (0201 (0603M) Capacitor)
pins: 1, 2

## GRM0335C1H221FA01D
designator C?  Capacitance: 220pF  (hidden comment: *)
Capacitor, Ceramic (MLCC), 220pF, ±1%, 50V, ±1%, SMD 0201; Manufacturer: Murata Electronics; Manufacturer Part Number: GRM0335C1H221FA01D
footprint CAP-0201 (0201 (0603M) Capacitor)
pins: 1, 2

## GRM0335C1H270FA01D
designator C?  Capacitance: 27pF  (hidden comment: *)
Capacitor, Ceramic (MLCC), 27pF, ±1%, 50V, C0G, ±1%, SMD 0201; Manufacturer: Murata Electronics; Manufacturer Part Number: GRM0335C1H270FA01D
footprint CAP-0201 (0201 (0603M) Capacitor)
pins: 1, 2

## GRM0335C1H270GA01D
designator C?  Capacitance: 27pF  (hidden comment: *)
Capacitor, Ceramic (MLCC), 27pF, ±2%, 50V, C0G, ±2%, SMD 0201; Manufacturer: Murata Electronics; Manufacturer Part Number: GRM0335C1H270GA01D
footprint CAP-0201 (0201 (0603M) Capacitor)
pins: 1, 2

## GRM0335C1H270JA01D
designator C?  Capacitance: 27pF  (hidden comment: *)
Capacitor, Ceramic (MLCC), 27pF, ±5%, 50V, C0G, ±5%, SMD 0201; Manufacturer: Murata Electronics; Manufacturer Part Number: GRM0335C1H270JA01D
footprint CAP-0201 (0201 (0603M) Capacitor)
pins: 1, 2

## GRM0335C1H300FA01D
designator C?  Capacitance: 30pF  (hidden comment: *)
Capacitor, Ceramic (MLCC), 30pF, ±1%, 50V, C0G, ±1%, SMD 0201; Manufacturer: Murata Electronics; Manufacturer Part Number: GRM0335C1H300FA01D
footprint CAP-0201 (0201 (0603M) Capacitor)
pins: 1, 2

## GRM0335C1H330JA01D
designator C?  Capacitance: 33pF  (hidden comment: *)
Capacitor, Ceramic (MLCC), 33pF, ±5%, 50V, C0G, ±5%, SMD 0201; Manufacturer: Murata Electronics; Manufacturer Part Number: GRM0335C1H330JA01D
footprint CAP-0201 (0201 (0603M) Capacitor)
pins: 1, 2

## GRM0335C1H360JA01D
designator C?  Capacitance: 36pF  (hidden comment: *)
Capacitor, Ceramic (MLCC), 36pF, ±5%, 50V, C0G, ±5%, SMD 0201; Manufacturer: Murata Electronics; Manufacturer Part Number: GRM0335C1H360JA01D
footprint CAP-0201 (0201 (0603M) Capacitor)
pins: 1, 2

## GRM0335C1H390JA01D
designator C?  Capacitance: 39pF  (hidden comment: *)
Capacitor, Ceramic (MLCC), 39pF, ±5%, 50V, C0G, ±5%, SMD 0201; Manufacturer: Murata Electronics; Manufacturer Part Number: GRM0335C1H390JA01D
footprint CAP-0201 (0201 (0603M) Capacitor)
pins: 1, 2

## GRM0335C1H430GA01D
designator C?  Capacitance: 43pF  (hidden comment: *)
Capacitor, Ceramic (MLCC), 43pF, ±2%, 50V, C0G, ±2%, SMD 0201; Manufacturer: Murata Electronics; Manufacturer Part Number: GRM0335C1H430GA01D
footprint CAP-0201 (0201 (0603M) Capacitor)
pins: 1, 2

## GRM0335C1H560GA01D
designator C?  Capacitance: 56pF  (hidden comment: *)
Capacitor, Ceramic (MLCC), 56pF, ±2%, 50V, C0G, ±2%, SMD 0201; Manufacturer: Murata Electronics; Manufacturer Part Number: GRM0335C1H560GA01D
footprint CAP-0201 (0201 (0603M) Capacitor)
pins: 1, 2

## GRM0335C1H560JA01D
designator C?  Capacitance: 56pF  (hidden comment: *)
Capacitor, Ceramic (MLCC), 56pF, ±5%, 50V, C0G, ±5%, SMD 0201; Manufacturer: Murata Electronics; Manufacturer Part Number: GRM0335C1H560JA01D
footprint CAP-0201 (0201 (0603M) Capacitor)
pins: 1, 2

## GRM0335C1H620JA01D
designator C?  Capacitance: 62pF  (hidden comment: *)
Capacitor, Ceramic (MLCC), 62pF, ±5%, 50V, C0G, ±5%, SMD 0201; Manufacturer: Murata Electronics; Manufacturer Part Number: GRM0335C1H620JA01D
footprint CAP-0201 (0201 (0603M) Capacitor)
pins: 1, 2

## GRM0335C1H680GA01D
designator C?  Capacitance: 68pF  (hidden comment: *)
Capacitor, Ceramic (MLCC), 68pF, ±2%, 50V, C0G, ±2%, SMD 0201; Manufacturer: Murata Electronics; Manufacturer Part Number: GRM0335C1H680GA01D
footprint CAP-0201 (0201 (0603M) Capacitor)
pins: 1, 2

## GRM0335C1H820GA01D
designator C?  Capacitance: 82pF  (hidden comment: *)
Capacitor, Ceramic (MLCC), 82pF, ±2%, 50V, C0G, ±2%, SMD 0201; Manufacturer: Murata Electronics; Manufacturer Part Number: GRM0335C1H820GA01D
footprint CAP-0201 (0201 (0603M) Capacitor)
pins: 1, 2

## GRM0335C1HR20BA01D
designator C?  Capacitance: 0.2pF  (hidden comment: *)
Capacitor, Ceramic (MLCC), 0.2pF, ±0.1pF, 50V, C0G, ±0.1pF, SMD 0201; Manufacturer: Murata Electronics; Manufacturer Part Number: GRM0335C1HR20BA01D
footprint CAP-0201 (0201 (0603M) Capacitor)
pins: 1, 2

## GRM0335C1HR30BA01D
designator C?  Capacitance: 0.3pF  (hidden comment: *)
Capacitor, Ceramic (MLCC), 0.3pF, ±0.1pF, 50V, C0G, ±0.1pF, SMD 0201; Manufacturer: Murata Electronics; Manufacturer Part Number: GRM0335C1HR30BA01D
footprint CAP-0201 (0201 (0603M) Capacitor)
pins: 1, 2

## GRM0335C1HR30WA01D
designator C?  Capacitance: 0.3pF  (hidden comment: *)
Capacitor, Ceramic (MLCC), 0.3pF, ±0.05pF, 50V, C0G, ±0.05pF, SMD 0201; Manufacturer: Murata Electronics; Manufacturer Part Number: GRM0335C1HR30WA01D
footprint CAP-0201 (0201 (0603M) Capacitor)
pins: 1, 2

## GRM0335C1HR40BA01D
designator C?  Capacitance: 0.4pF  (hidden comment: *)
Capacitor, Ceramic (MLCC), 0.4pF, ±0.1pF, 50V, C0G, ±0.1pF, SMD 0201; Manufacturer: Murata Electronics; Manufacturer Part Number: GRM0335C1HR40BA01D
footprint CAP-0201 (0201 (0603M) Capacitor)
pins: 1, 2

## GRM0335C1HR50BA01D
designator C?  Capacitance: 0.5pF  (hidden comment: *)
Capacitor, Ceramic (MLCC), 0.5pF, ±0.1pF, 50V, C0G, ±0.1pF, SMD 0201; Manufacturer: Murata Electronics; Manufacturer Part Number: GRM0335C1HR50BA01D
footprint CAP-0201 (0201 (0603M) Capacitor)
pins: 1, 2

## GRM0335C1HR60BA01D
designator C?  Capacitance: 0.6pF  (hidden comment: *)
Capacitor, Ceramic (MLCC), 0.6pF, ±0.1pF, 50V, C0G, ±0.1pF, SMD 0201; Manufacturer: Murata Electronics; Manufacturer Part Number: GRM0335C1HR60BA01D
footprint CAP-0201 (0201 (0603M) Capacitor)
pins: 1, 2

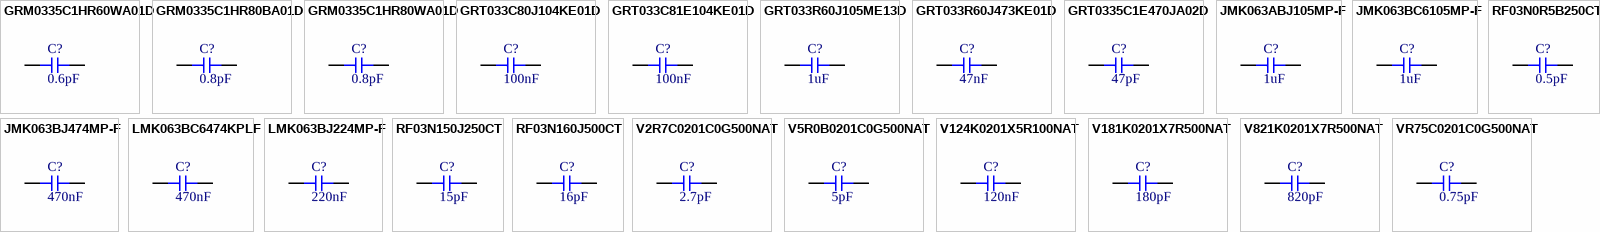
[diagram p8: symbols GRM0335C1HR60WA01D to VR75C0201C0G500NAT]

## GRM0335C1HR60WA01D
designator C?  Capacitance: 0.6pF  (hidden comment: *)
Capacitor, Ceramic (MLCC), 0.6pF, SMD 0201; Manufacturer: Murata Electronics; Manufacturer Part Number: GRM0335C1HR60WA01D
footprint CAP-0201 (0201 (0603M) Capacitor)
pins: 1, 2

## GRM0335C1HR80BA01D
designator C?  Capacitance: 0.8pF  (hidden comment: *)
Capacitor, Ceramic (MLCC), 0.8pF, ±0.1pF, 50V, C0G, ±0.1pF, SMD 0201; Manufacturer: Murata Electronics; Manufacturer Part Number: GRM0335C1HR80BA01D
footprint CAP-0201 (0201 (0603M) Capacitor)
pins: 1, 2

## GRM0335C1HR80WA01D
designator C?  Capacitance: 0.8pF  (hidden comment: *)
Capacitor, Ceramic (MLCC), 0.8pF, SMD 0201; Manufacturer: Murata Electronics; Manufacturer Part Number: GRM0335C1HR80WA01D
footprint CAP-0201 (0201 (0603M) Capacitor)
pins: 1, 2

## GRT033C80J104KE01D
designator C?  Capacitance: 100nF  (hidden comment: *)
Capacitor, Ceramic (MLCC), 100nF, ±10%, ±10%, SMD 0201; Manufacturer: Murata Electronics; Manufacturer Part Number: GRT033C80J104KE01D
footprint CAP-0201 (0201 (0603M) Capacitor)
pins: 1, 2

## GRT033C81E104KE01D
designator C?  Capacitance: 100nF  (hidden comment: *)
Capacitor, Ceramic (MLCC), 100nF, ±10%, 25V, X6S, ±10%, SMD 0201; Manufacturer: Murata Electronics; Manufacturer Part Number: GRT033C81E104KE01D
footprint CAP-0201 (0201 (0603M) Capacitor)
pins: 1, 2

## GRT033R60J105ME13D
designator C?  Capacitance: 1uF  (hidden comment: *)
Capacitor, Ceramic (MLCC), 1uF, ±20%, 6.3V, X5R, ±20%, SMD 0201; Manufacturer: Murata Electronics; Manufacturer Part Number: GRT033R60J105ME13D
footprint CAP-0201 (0201 (0603M) Capacitor)
pins: 1, 2

## GRT033R60J473KE01D
designator C?  Capacitance: 47nF  (hidden comment: *)
Capacitor, Ceramic (MLCC), 47nF, ±10%, 6.3V, X5R, ±10%, SMD 0201; Manufacturer: Murata Electronics; Manufacturer Part Number: GRT033R60J473KE01D
footprint CAP-0201 (0201 (0603M) Capacitor)
pins: 1, 2

## GRT0335C1E470JA02D
designator C?  Capacitance: 47pF  (hidden comment: *)
Capacitor, Ceramic (MLCC), 47pF, ±5%, ±5%, SMD 0201; Manufacturer: Murata Electronics; Manufacturer Part Number: GRT0335C1E470JA02D
footprint CAP-0201 (0201 (0603M) Capacitor)
pins: 1, 2

## JMK063ABJ105MP-F
designator C?  Capacitance: 1uF  (hidden comment: *)
Capacitor, Ceramic (MLCC), 1uF, ±20%, 6.3V, X5R, ±20%, SMD 0201; Manufacturer: Taiyo Yuden; Manufacturer Part Number: JMK063ABJ105MP-F
footprint CAP-0201 (0201 (0603M) Capacitor)
pins: 1, 2

## JMK063BC6105MP-F
designator C?  Capacitance: 1uF  (hidden comment: *)
Capacitor, Ceramic (MLCC), 1uF, ±20%, ±20%, SMD 0201; Manufacturer: Taiyo Yuden; Manufacturer Part Number: JMK063BC6105MP-F
footprint CAP-0201 (0201 (0603M) Capacitor)
pins: 1, 2

## JMK063BJ474MP-F
designator C?  Capacitance: 470nF  (hidden comment: *)
Capacitor, Ceramic (MLCC), 470nF, ±20%, 6.3V, X5R, ±20%, SMD 0201; Manufacturer: Taiyo Yuden; Manufacturer Part Number: JMK063BJ474MP-F
footprint CAP-0201 (0201 (0603M) Capacitor)
pins: 1, 2

## LMK063BC6474KPLF
designator C?  Capacitance: 470nF  (hidden comment: *)
Capacitor, Ceramic (MLCC), 470nF, ±10%, 10V, ±10%, SMD 0201; Manufacturer: Taiyo Yuden; Manufacturer Part Number: LMK063BC6474KPLF
footprint CAP-0201 (0201 (0603M) Capacitor)
pins: 1, 2

## LMK063BJ224MP-F
designator C?  Capacitance: 220nF  (hidden comment: *)
Capacitor, Ceramic (MLCC), 220nF, ±20%, 10V, X5R, ±20%, SMD 0201; Manufacturer: Taiyo Yuden; Manufacturer Part Number: LMK063BJ224MP-F
footprint CAP-0201 (0201 (0603M) Capacitor)
pins: 1, 2

## RF03N0R5B250CT
designator C?  Capacitance: 0.5pF  (hidden comment: *)
Capacitor, Ceramic (MLCC), 0.5pF, ±0.1pF, 25V, NP0, ±0.1pF, SMD 0201; Manufacturer: Walsin Tech Corp; Manufacturer Part Number: RF03N0R5B250CT
footprint CAP-0201 (0201 (0603M) Capacitor)
pins: 1, 2

## RF03N150J250CT
designator C?  Capacitance: 15pF  (hidden comment: *)
Capacitor, Ceramic (MLCC), 15pF, ±5%, 25V, NP0, ±5%, SMD 0201; Manufacturer: Walsin Tech Corp; Manufacturer Part Number: RF03N150J250CT
footprint CAP-0201 (0201 (0603M) Capacitor)
pins: 1, 2

## RF03N160J500CT
designator C?  Capacitance: 16pF  (hidden comment: *)
Capacitor, Ceramic (MLCC), 16pF, ±5%, 50V, NP0, ±5%, SMD 0201; Manufacturer: Walsin Tech Corp; Manufacturer Part Number: RF03N160J500CT
footprint CAP-0201 (0201 (0603M) Capacitor)
pins: 1, 2

## V2R7C0201C0G500NAT
designator C?  Capacitance: 2.7pF  (hidden comment: *)
Capacitor, Ceramic (MLCC), 2.7pF, ±0.25pF, 50V, C0G, ±0.25pF, SMD 0201; Manufacturer: VIIYONG; Manufacturer Part Number: V2R7C0201C0G500NAT
footprint CAP-0201 (0201 (0603M) Capacitor)
pins: 1, 2

## V5R0B0201C0G500NAT
designator C?  Capacitance: 5pF  (hidden comment: *)
Capacitor, Ceramic (MLCC), 5pF, ±0.1pF, 50V, C0G, ±0.1pF, SMD 0201; Manufacturer: VIIYONG; Manufacturer Part Number: V5R0B0201C0G500NAT
footprint CAP-0201 (0201 (0603M) Capacitor)
pins: 1, 2

## V124K0201X5R100NAT
designator C?  Capacitance: 120nF  (hidden comment: *)
Capacitor, Ceramic (MLCC), 120nF, ±10%, 10V, X5R, ±10%, SMD 0201; Manufacturer: VIIYONG; Manufacturer Part Number: V124K0201X5R100NAT
footprint CAP-0201 (0201 (0603M) Capacitor)
pins: 1, 2

## V181K0201X7R500NAT
designator C?  Capacitance: 180pF  (hidden comment: *)
Capacitor, Ceramic (MLCC), 180pF, ±10%, 50V, X7R, ±10%, SMD 0201; Manufacturer: VIIYONG; Manufacturer Part Number: V181K0201X7R500NAT
footprint CAP-0201 (0201 (0603M) Capacitor)
pins: 1, 2

## V821K0201X7R500NAT
designator C?  Capacitance: 820pF  (hidden comment: *)
Capacitor, Ceramic (MLCC), 820pF, ±10%, 50V, X7R, ±10%, SMD 0201; Manufacturer: VIIYONG; Manufacturer Part Number: V821K0201X7R500NAT
footprint CAP-0201 (0201 (0603M) Capacitor)
pins: 1, 2

## VR75C0201C0G500NAT
designator C?  Capacitance: 0.75pF  (hidden comment: *)
Capacitor, Ceramic (MLCC), 0.75pF, ±0.25pF, 50V, C0G, ±0.25pF, SMD 0201; Manufacturer: VIIYONG; Manufacturer Part Number: VR75C0201C0G500NAT
footprint CAP-0201 (0201 (0603M) Capacitor)
pins: 1, 2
